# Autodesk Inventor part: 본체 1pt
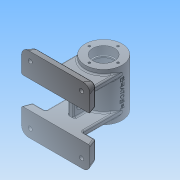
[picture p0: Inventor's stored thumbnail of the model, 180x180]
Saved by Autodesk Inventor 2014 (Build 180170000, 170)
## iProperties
Created: 2016-07
Part Number: 본체 1pt
Material: 일반
Document SubType Name: Modeling
Designer: NET
Density: 1 g/cm^3
Appearance: 기본값
Author: NET
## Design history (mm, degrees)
sketch "스케치1"
  geometry: C1 r 27 at (0, 0); 1 further point
  constraints: 1 centre point, 1 coincident
  dimensions: "d0" = 54 diameter of C1
extrude "돌출1" new body sketch "스케치1" stored distance "d1" = 70; taper "d2" = 0 deg
sketch "스케치2"
  geometry: C1 r 27 at (0, 0) reference; C2 r 16 at (0, 0)
  constraints: 1 centre point, 1 coincident
  dimensions: "d3" = 32 diameter of C2
extrude "돌출2" cut sketch "스케치2" distance "d4" = 12; taper "d5" = 0 deg
sketch "스케치3"
  geometry: C1 r 22 at (0, 0); 1 further point
  constraints: 1 centre point, 1 coincident
  dimensions: "d6" = 44 diameter of C1
extrude "돌출3" cut sketch "스케치3" stored distance "d7" = 42; taper "d8" = 0 deg
sketch "스케치4"
  geometry: C1 r 16 at (0, 0) reference; C2 r 14 at (0, 0)
  constraints: 1 centre point, 1 coincident
  dimensions: "d9" = 28 diameter of C2
extrude "돌출4" cut sketch "스케치4" stored distance "d10" = 42; taper "d11" = 0 deg
node "작업 평면2"
sketch "스케치5"
  geometry: L1 (-50, 55)-(50, 55); L2 (50, 55)-(50, 20); L3 (50, 20)-(-50, 20); L4 (-50, 20)-(-50, 55); L5 (-50, -20)-(50, -20); L6 (50, -20)-(50, -55); L7 (50, -55)-(-50, -55); L8 (-50, -55)-(-50, -20); L9 (-27, -20)-(27, -20); L10 (27, -20)-(27, -28); L11 (27, -28)-(-27, -28); L12 (-27, -28)-(-27, -20); L13 (-27, 20)-(27, 20); L14 (27, 20)-(27, 28); L15 (27, 28)-(-27, 28); L16 (-27, 28)-(-27, 20); 4 further points
  constraints: 32 end point, 8 parallel, 4 equal length, 4 horizontal, 4 midpoint, 4 perpendicular, 3 vertical alignment, 2 point on line
  dimensions: "d13" = 35 distance of L5.end L6.end; "d14" = 8 distance of L9.end L10.end; "d15" = 55 distance from line of point (0, 0) L1; "d16" = 100 distance between parallel lines of L2 L4; "d17" = 54 distance of L10.end L11.end; "d19" = 55 distance from line of point (0, 0) L7
extrude "돌출5" join sketch "스케치5" stored distance "d20" = 42; taper "d21" = 0 deg
sketch "스케치6"
  geometry: L1 (-40, 55)-(40, 55); L2 (50, 45)-(50, -45); L3 (40, -55)-(-40, -55); L4 (-50, -45)-(-50, 45); A1 r 10 centre (-40, -45) between (-50, -45) and (-40, -55); A2 r 10 centre (-40, 45) between (-40, 55) and (-50, 45); A3 r 10 centre (40, 45) between (50, 45) and (40, 55); A4 r 10 centre (40, -45) between (40, -55) and (50, -45); 7 further points
  constraints: 8 end point, 8 point on circle, 8 point on line, 8 tangent, 4 centre point, 3 equal radius, 2 midpoint, 2 parallel, 1 horizontal, 1 horizontal alignment, 1 perpendicular, 1 vertical alignment
  dimensions: "d22" = 100 distance of point (50, -55) point (-50, -55); "d23" = 110 distance of point (50, 55) point (50, -55); "d68" = 10 radius of A1
extrude "돌출6" join sketch "스케치6" distance "d24" = 12; taper "d25" = -20 deg
sketch "스케치7"
  geometry: L1 (-50, -45)-(-50, 45) reference; L2 (50, 45)-(50, -45) reference; L3 (-50, 20)-(50, 20); L4 (50, 20)-(50, -20); L5 (50, -20)-(-50, -20); L6 (-50, -20)-(-50, 20); 5 further points
  constraints: 8 end point, 2 parallel, 2 point on line, 1 horizontal, 1 perpendicular
extrude "돌출7" cut sketch "스케치7" distance "d26" = 12; taper "d27" = 0 deg
node "작업 평면3"
sketch "스케치8"
  geometry: L1 (27, 35)-(-27, 35) reference; C1 r 5 at (0, 13); 1 further point
  constraints: 1 centre point, 1 vertical alignment
  dimensions: "d29" = 22 distance from line of L1 C1.centre; "d30" = 10 diameter of C1
extrude "돌출8" join sketch "스케치8" stored distance "d31" = 12; taper "d32" = 0 deg
node "작업 평면4"
sketch "스케치9"
  geometry: L1 (-50, -20)-(50, -20) reference; L2 (50, 20)-(-50, 20) reference; L3 (-4, 20)-(4, 20); L4 (4, 20)-(4, -20); L5 (4, -20)-(-4, -20); L6 (-4, -20)-(-4, 20); 3 further points
  constraints: 8 end point, 2 midpoint, 2 parallel, 2 point on line, 1 coincident, 1 horizontal, 1 perpendicular
  dimensions: "d34" = 8 distance between parallel lines of L4 L6
extrude "돌출9" join sketch "스케치9" stored distance "d35" = 12; taper "d36" = 0 deg
sketch "스케치10"
  geometry: L1 (0, 21.298)-(40, 21.298) reference; L2 (12, 10)-(28, 10); L3 (12, 6.5)-(28, 6.5); L4 (28, 13.5)-(12, 13.5); L5 (65, -22)-(40, -22) reference; A1 r 3.5 centre (12, 10) between (12, 13.5) and (12, 6.5); A2 r 3.5 centre (28, 10) between (28, 6.5) and (28, 13.5); 4 further points
  constraints: 8 end point, 4 point on circle, 4 tangent, 2 centre point, 2 midpoint, 2 parallel, 1 vertical alignment
  dimensions: "d37" = 3.5 radius of A2; "d38" = 23 dimension on A2 A1; "d39" = 32 distance from line of L5 point (20, 10)
extrude "돌출10" cut sketch "스케치10" stored distance "d40" = 12; taper "d41" = 0 deg
sketch "스케치11"
  geometry: L1 (0, 0)-(-15.898, -25.441); L2 (0, 0)-(0, -16.13)
  constraints: 4 end point, 1 vertical
  dimensions: "d42" = 30 distance of L1.start L1.end; "d43" = 32 deg angle of L2 L1
node "작업 평면5"
sketch "스케치12"
  geometry: C1 r 6 at (0, 0); 1 further point
  constraints: 1 centre point, 1 coincident
  dimensions: "d44" = 12 diameter of C1
extrude "돌출11" join sketch "스케치12" stored distance "d45" = 12; taper "d46" = 0 deg
hole "구멍1" diameter "d49" = 6; stored, may be unused: countersink angle "d53" = 90 deg, drill point angle "d55" = 118 deg; dims "d47" = 12.5, "d48" = 1, "d50" = 6, "d51" = 10, "d52" = 4, "d54" = 8
node "작업 평면6"
sketch "스케치13"
  geometry: L1 (27, -35)-(27, 35) reference; 2 further points
  constraints: 1 coincident, 1 other
  dimensions: "d63" = 27 distance from line of point (0, 0) L1 (derived); "d64" = 35 vertical distance of L1.end point (0, 0) (derived)
feature "엠보싱1" sketch "스케치13" dims "d9" = 28, "d65" = 0.5, "d66" = 0
fillet "모깎기1" dims "d67" = 2
fillet "모깎기2" dims "d75" = 2
hole "구멍2" diameter "d78" = 5.188; stored, may be unused: countersink angle "d82" = 90 deg, drill point angle "d84" = 118 deg; dims "d76" = 10, "d77" = 10, "d79" = 6, "d80" = 10, "d81" = 4, "d83" = 8
hole "구멍3" diameter "d87" = 5.188; stored, may be unused: countersink angle "d91" = 90 deg, drill point angle "d93" = 118 deg; dims "d85" = 10, "d86" = 10, "d88" = 6, "d89" = 10, "d90" = 4, "d92" = 8
sketch "스케치14"
  geometry: C1 r 16 at (0, 0) reference; 1 further point
  constraints: 1 horizontal alignment
  dimensions: "d94" = 21 distance of C1.centre point (-21, 0)
hole "구멍4" sketch "스케치14" at (-21, 0) diameter "d95" = 3.242; stored, may be unused: countersink angle "d99" = 90 deg, drill point angle "d101" = 118 deg; dims "d96" = 8, "d97" = 10, "d98" = 4, "d100" = 10
node "솔리드1"
mirror "대칭1"
pattern_linear "직사각형 패턴2" dims "d71" = 85, "d74" = 75
pattern_circular "원형 패턴1" dims angle "d103" = 360 deg
mirror "대칭2"
node "작업 평면1"
node "작업 평면7"
other parameters: "d33" = -48
